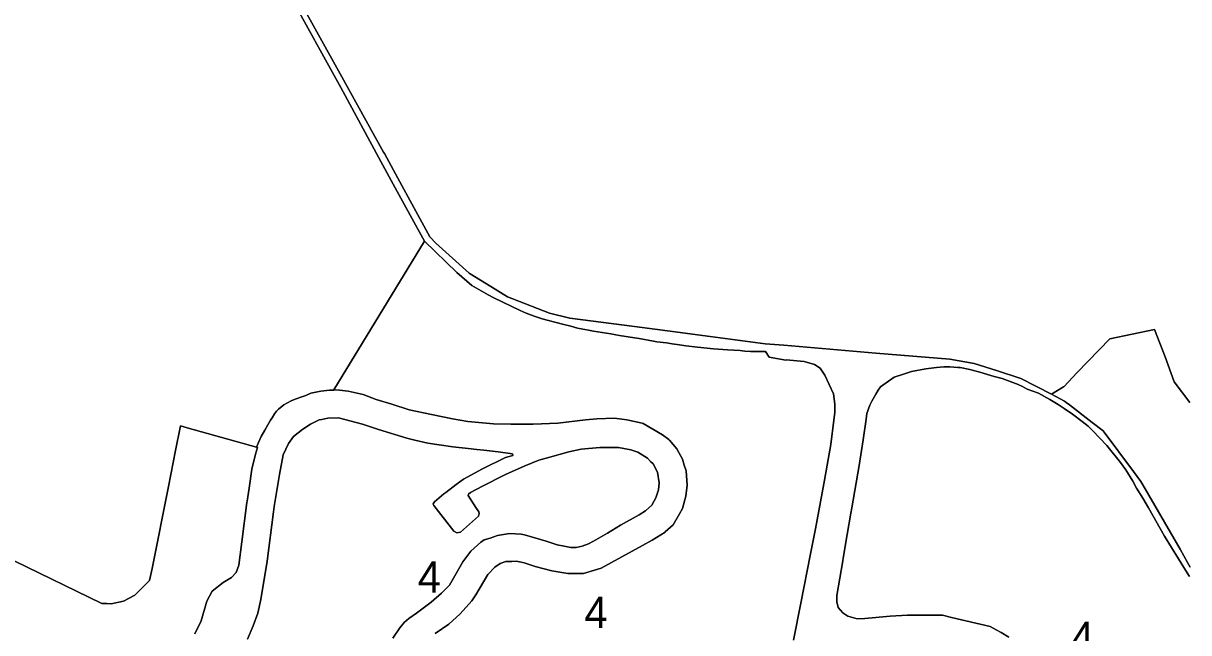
# Model space of a CAD drawing. Extents: x 598968 to 613553, y 4409678 to 4430833.
# Drawn here: x 610893 to 611339.8, y 4416609.3 to 4416843 of the extents above; entities that cross this region are included whole.
import ezdxf

# ---------------------------------------------------------------- set-up
doc = ezdxf.new("R2010")
doc.units = 0
for name, color, linetype in [('1', 7, 'Continuous'), ('Sòl Rústic Protegit', 7, 'Continuous'), ('Sòl Rústic Protegit - Alt Nivell de Protecció', 7, 'Continuous'), ('ZONA 4. CASES UNIFAMILIRAS AÏLLADES EN PARCEL.LES', 7, 'Continuous')]:
    doc.layers.add(name, color=color, linetype=linetype)

msp = doc.modelspace()

# ---------------------------------------------------------------- linework, layer by layer
at = {"layer": '1'}
for points in [[(611340.4703, 4416634.3506), (611339.421, 4416636.193), (611336.5169, 4416641.2922), (611332.8661, 4416647.7024), (611322.2536, 4416666.0055), (611321.4964, 4416667.3114), (611318.6806, 4416671.0975), (611307.1066, 4416686.6604), (611302.8637, 4416689.9208), (611294.1748, 4416696.5975), (611292.8617, 4416697.6065), (611292.207, 4416698.1096), (611287.2312, 4416700.7078), (611275.5474, 4416706.8087), (611266.1752, 4416709.7685), (611266.1698, 4416709.7702), (611257.6278, 4416712.4679), (611248.2281, 4416714.1276), (611219.9061, 4416716.5237), (611211.1119, 4416717.2678), (611184.6606, 4416719.5056), (611177.4599, 4416720.1149), (611156.3914, 4416722.8816), (611140.0057, 4416725.0334), (611135.0952, 4416725.6783), (611127.416, 4416726.6867), (611102.5516, 4416729.952), (611094.7018, 4416731.7716), (611080.3379, 4416737.4735), (611078.6822, 4416738.1308), (611072.3046, 4416742.0605), (611064.399, 4416746.9319), (611064.0125, 4416747.17), (611051.1328, 4416758.6293), (611048.8928, 4416761.0792), (611036.6372, 4416783.5263), (611031.4692, 4416792.9921), (611031.1632, 4416793.5526), (611014.5492, 4416823.542), (610996.5766, 4416855.9839)], [(610889.5487, 4416636.874), (610923.0883, 4416620.5149), (610924.9787, 4416620.4311), (610926.6983, 4416620.3549), (610931.4782, 4416621.355), (610935.7282, 4416623.715), (610941.4481, 4416629.2451), (610942.3873, 4416633.9202), (610948.6979, 4416665.3346), (610951.3988, 4416679.184), (610953.2378, 4416688.6144), (610955.7762, 4416687.8964), (610982.3887, 4416680.369), (610982.4015, 4416680.3985), (610982.4647, 4416680.5442), (610982.5502, 4416680.7415), (610983.1674, 4416682.1651), (610984.1574, 4416684.555), (610985.6274, 4416686.995), (610986.7073, 4416688.955), (610987.7473, 4416690.755), (610988.4873, 4416691.725), (610989.3173, 4416693.195), (610990.0973, 4416694.265), (610990.9073, 4416694.955), (610992.9572, 4416696.705), (610995.6972, 4416698.2051), (610997.2872, 4416698.8151), (611000.1972, 4416699.8851), (611001.3871, 4416700.2451), (611003.2871, 4416701.1652), (611007.0471, 4416701.8952), (611010.417, 4416702.3353), (611012.047, 4416702.3252), (611012.067, 4416702.3582), (611046.7764, 4416759.3851), (611042.6965, 4416766.8549), (611035.6093, 4416779.9183), (611030.1391, 4416790.0016), (611014.7467, 4416818.3737), (611012.8397, 4416821.8304), (610996.9169, 4416850.6929)], [(610996.9169, 4416850.6929), (611012.8397, 4416821.8304), (611014.7467, 4416818.3737), (611030.1391, 4416790.0016), (611035.6093, 4416779.9183), (611042.6965, 4416766.8549), (611046.7764, 4416759.3851), (611059.1863, 4416747.4354), (611064.9462, 4416742.4157), (611071.2962, 4416738.8158), (611073.4561, 4416737.7259), (611083.536, 4416732.8361), (611085.866, 4416731.7662), (611088.856, 4416730.6062), (611091.9159, 4416729.6363), (611099.7158, 4416727.5865), (611102.9558, 4416726.8865), (611105.5459, 4416726.0466), (611109.6958, 4416725.2367), (611111.6458, 4416724.8867), (611118.3357, 4416723.8269), (611120.2557, 4416723.4469), (611121.6057, 4416723.2169), (611127.3756, 4416722.387), (611129.1956, 4416722.0871), (611134.6355, 4416721.0971), (611135.8855, 4416720.8672), (611139.6254, 4416720.4173), (611141.8554, 4416720.0673), (611144.6454, 4416719.6374), (611146.9953, 4416719.2774), (611151.5553, 4416718.8075), (611157.6852, 4416718.1976), (611163.0251, 4416717.7977), (611167.8151, 4416717.4778), (611169.7151, 4416717.2179), (611171.895, 4416717.1479), (611177.615, 4416717.158), (611179.0049, 4416714.9481), (611185.3849, 4416713.8182), (611185.4549, 4416713.9782), (611192.4048, 4416713.2983), (611196.3947, 4416712.1883), (611198.5247, 4416710.7584), (611200.3647, 4416708.0385), (611203.6247, 4416700.8987), (611204.2143, 4416696.8614), (611204.1747, 4416693.7418), (611203.1591, 4416685.6628), (611202.6247, 4416681.412), (611200.2248, 4416667.8221), (611199.9648, 4416666.3422), (611196.7049, 4416649.1023), (611194.8949, 4416639.5124), (611191.175, 4416620.6127), (611188.325, 4416606.3928)], [(611270.9439, 4416607.5643), (611268.004, 4416609.3142), (611265.984, 4416610.4342), (611263.724, 4416611.6541), (611248.8729, 4416615.1396), (611245.4043, 4416615.9537), (611240.1644, 4416615.9936), (611236.7244, 4416616.0135), (611233.5945, 4416616.0335), (611231.9744, 4416615.943), (611225.3646, 4416615.6534), (611215.6947, 4416614.6932), (611212.7847, 4416614.5932), (611209.1048, 4416615.5631), (611207.2248, 4416616.883), (611205.4148, 4416618.933), (611204.8855, 4416621.1303), (611204.9348, 4416623.5098), (611207.1847, 4416636.8497), (611207.356, 4416637.8394), (611208.9347, 4416646.9595), (611210.3347, 4416655.1094), (611210.7047, 4416657.1494), (611213.4722, 4416673.4296), (611215.0446, 4416683.2991), (611216.1645, 4416691.179), (611216.4945, 4416693.399), (611217.5345, 4416696.469), (611218.3945, 4416698.069), (611219.9145, 4416700.7589), (611220.8444, 4416702.2889), (611221.6344, 4416703.559), (611226.9144, 4416707.269), (611230.4843, 4416708.3891), (611233.5543, 4416709.4591), (611239.1243, 4416710.5091), (611243.0941, 4416710.9992), (611245.9041, 4416711.2792), (611248.2641, 4416711.1793), (611251.3546, 4416710.9823), (611252.184, 4416710.9294), (611255.934, 4416710.2495), (611259.7339, 4416709.1296), (611265.2338, 4416707.5897), (611268.2938, 4416706.7797), (611274.4437, 4416704.4699), (611276.0637, 4416703.6399), (611277.8937, 4416702.7), (611282.3036, 4416701.0801), (611286.6536, 4416698.7002), (611289.8235, 4416696.8203), (611292.0735, 4416695.2203), (611295.2935, 4416693.0904), (611298.9434, 4416690.3305), (611301.2734, 4416688.4506), (611303.0234, 4416686.8306), (611308.4933, 4416681.0708), (611313.6633, 4416674.491), (611315.7732, 4416671.781), (611318.4332, 4416667.3412), (611319.8732, 4416664.6512), (611322.2833, 4416660.9213), (611324.3932, 4416657.1214), (611330.6232, 4416646.2417), (611338.663, 4416633.2021), (611340.133, 4416630.8421)], [(611050.9267, 4416608.9704), (611056.1466, 4416612.5804), (611060.4866, 4416616.4804), (611064.9765, 4416621.5204), (611066.4565, 4416623.7704), (611071.1764, 4416631.5504), (611073.8063, 4416634.4304), (611075.9063, 4416635.7805), (611078.0263, 4416636.5705), (611080.3363, 4416636.6405), (611081.9662, 4416636.6905), (611083.8962, 4416636.2605), (611085.0062, 4416636.0106), (611089.2762, 4416634.6207), (611095.6961, 4416632.9908), (611101.796, 4416631.9409), (611107.786, 4416631.9611), (611112.076, 4416633.3011), (611114.5159, 4416634.0712), (611130.3657, 4416642.7313), (611134.1657, 4416644.8114), (611139.1056, 4416647.8914), (611139.1056, 4416647.9114), (611142.1455, 4416650.6914), (611144.5655, 4416654.8913), (611145.7655, 4416656.9613), (611147.0855, 4416661.6113), (611147.5539, 4416665.897), (611147.5554, 4416665.9112), (611147.1054, 4416671.3312), (611146.4454, 4416673.5811), (611145.7854, 4416675.811), (611143.5855, 4416679.7909), (611140.8055, 4416683.1508), (611140.5055, 4416683.3709), (611138.0855, 4416685.2008), (611130.6563, 4416689.4622), (611130.2556, 4416689.6606), (611124.4457, 4416690.9505), (611119.7057, 4416691.4904), (611112.8758, 4416691.3202), (611108.5659, 4416690.9302), (611098.0059, 4416689.59), (611088.4661, 4416689.1999), (611080.3462, 4416689.1997), (611079.8862, 4416689.1997), (611073.2962, 4416689.3896), (611063.4564, 4416690.3194), (611057.5364, 4416691.2892), (611049.5766, 4416692.9391), (611041.0066, 4416694.769), (611034.3168, 4416696.8789), (611028.3568, 4416698.7587), (611023.297, 4416700.5786), (611017.5669, 4416701.9484), (611014.207, 4416702.3484), (611012.067, 4416702.3582), (611012.047, 4416702.3252), (611010.417, 4416702.3353), (611007.0471, 4416701.8952), (611003.2871, 4416701.1652), (611001.3871, 4416700.2451), (611000.1972, 4416699.8851), (610997.2872, 4416698.8151), (610995.6972, 4416698.2051), (610992.9572, 4416696.705), (610990.9073, 4416694.955), (610990.0973, 4416694.265), (610989.3173, 4416693.195), (610988.4873, 4416691.725), (610987.7473, 4416690.755), (610986.7073, 4416688.955), (610985.6274, 4416686.995), (610984.1574, 4416684.555), (610983.1674, 4416682.1651), (610982.5502, 4416680.7415), (610982.4647, 4416680.5442), (610982.4015, 4416680.3985), (610982.3887, 4416680.369), (610982.8415, 4416680.241), (610982.0604, 4416677.7468), (610980.6737, 4416671.9346), (610979.5881, 4416664.7356), (610978.8224, 4416659.6596), (610978.7567, 4416659.1683), (610976.7394, 4416644.0765), (610975.6795, 4416635.1658), (610974.6425, 4416632.4005), (610972.8642, 4416630.4209), (610969.6222, 4416628.491), (610965.4134, 4416625.2367), (610963.35, 4416621.3341), (610961.184, 4416613.8732), (610958.7248, 4416608.878)], [(610978.9476, 4416606.7691), (610981.2076, 4416611.8791), (610982.9075, 4416616.8091), (610984.0775, 4416621.999), (610986.4575, 4416636.6989), (610988.9574, 4416655.6586), (610989.2175, 4416657.6086), (610991.2173, 4416669.9584), (610992.6473, 4416677.4583), (610994.7273, 4416681.8583), (610996.6372, 4416684.4883), (611000.1972, 4416687.3683), (611003.0971, 4416689.2984), (611006.4571, 4416690.8484), (611007.4771, 4416691.0984), (611009.807, 4416691.5985), (611013.827, 4416691.7285), (611023.0647, 4416689.2135), (611029.1468, 4416687.2188), (611040.008, 4416683.8504), (611043.1059, 4416683.1374), (611048.069, 4416681.9888), (611052.4228, 4416681.3347), (611057.7561, 4416680.588), (611063.625, 4416679.9563), (611066.9439, 4416679.5347), (611069.5442, 4416679.3003), (611075.045, 4416678.6424), (611080.6234, 4416677.8685), (611080.7396, 4416677.2879), (611080.7334, 4416677.286), (611077.8462, 4416676.4399), (611069.0863, 4416672.1198), (611061.8064, 4416668.1997), (611058.9865, 4416666.0497), (611055.0766, 4416663.0796), (611054.2365, 4416662.5696), (611050.6566, 4416659.5096), (611050.2166, 4416658.6396), (611050.2233, 4416658.62), (611050.2166, 4416658.6066), (611050.4266, 4416657.9966), (611058.1265, 4416648.1669), (611059.2165, 4416647.6069), (611060.6565, 4416647.8169), (611067.5964, 4416653.9269), (611067.828, 4416654.9358), (611067.8236, 4416654.9498), (611067.828, 4416654.9688), (611067.6164, 4416655.6499), (611066.5464, 4416657.2499), (611063.6374, 4416661.9083), (611063.6526, 4416662.3967), (611064.4139, 4416663.0336), (611069.0241, 4416665.5173), (611077.4062, 4416669.6469), (611078.1562, 4416670.0769), (611080.2562, 4416670.9369), (611085.0461, 4416673.157), (611090.736, 4416675.4971), (611094.8738, 4416676.5688), (611102.1159, 4416678.6872), (611106.8772, 4416679.6225), (611114.0335, 4416680.2608), (611120.1358, 4416680.3375), (611121.1851, 4416680.2936), (611126.0026, 4416679.3605), (611128.6358, 4416678.5677), (611132.2956, 4416676.2478), (611133.5056, 4416674.9478), (611134.5456, 4416673.9878), (611136.1517, 4416670.855), (611136.8734, 4416666.7403), (611136.5956, 4416664.0811), (611135.5756, 4416661.0211), (611133.9856, 4416658.1511), (611131.6358, 4416656.0011), (611129.1757, 4416654.4411), (611121.9958, 4416650.531), (611117.0599, 4416647.5017), (611111.6924, 4416644.4325), (611109.766, 4416643.3309), (611107.2785, 4416642.4112), (611105.0488, 4416642.0011), (611102.896, 4416641.9808), (611100.3533, 4416642.4852), (611097.7457, 4416643.0302), (611093.4851, 4416644.3309), (611091.2608, 4416645.0268), (611085.2262, 4416646.8405), (611083.9261, 4416647.0197), (611079.4488, 4416647.257), (611074.8684, 4416646.5091), (611072.0609, 4416645.5486), (611069.7464, 4416644.9302), (611068.4264, 4416644.0202), (611064.6302, 4416640.5255), (611063.4116, 4416638.9581), (611061.5972, 4416636.4496), (611056.3666, 4416627.5402), (611055.5366, 4416626.5702), (611053.3096, 4416624.4225), (611049.3371, 4416621.0065), (611043.7512, 4416616.7832), (611040.8344, 4416614.7402), (611039.0691, 4416613.232), (611037.339, 4416611.1665), (611034.741, 4416607.1495)], [(610958.7248, 4416608.878), (610961.184, 4416613.8732), (610963.35, 4416621.3341), (610965.4134, 4416625.2367), (610969.6222, 4416628.491), (610972.8642, 4416630.4209), (610974.6425, 4416632.4005), (610975.6795, 4416635.1658), (610976.7394, 4416644.0765), (610978.7567, 4416659.1683), (610978.8224, 4416659.6596), (610979.5881, 4416664.7356), (610980.6737, 4416671.9346), (610982.0604, 4416677.7468), (610982.8415, 4416680.241), (610982.3887, 4416680.369), (610955.7762, 4416687.8964), (610953.2378, 4416688.6144), (610951.3988, 4416679.184), (610948.6979, 4416665.3346), (610942.3873, 4416633.9202), (610941.4481, 4416629.2451), (610935.7282, 4416623.715), (610931.4782, 4416621.355), (610926.6983, 4416620.3549), (610924.9787, 4416620.4311), (610923.0883, 4416620.5149), (610889.5487, 4416636.874)]]:
    msp.add_lwpolyline(points, dxfattribs=at)
at = {"layer": 'Sòl Rústic Protegit'}
msp.add_lwpolyline([(611340.2427, 4416697.51), (611334.2427, 4416705.51), (611330.8051, 4416715.01), (611326.6801, 4416725.51), (611309.5551, 4416722.01), (611297.1177, 4416709.01), (611291.9927, 4416703.51), (611291.8677, 4416703.51), (611287.2312, 4416700.7078), (611292.207, 4416698.1096), (611292.8617, 4416697.6065), (611294.1748, 4416696.5975), (611302.8637, 4416689.9208), (611307.1066, 4416686.6604), (611318.6806, 4416671.0975), (611321.4964, 4416667.3114), (611322.2536, 4416666.0055), (611332.8661, 4416647.7024), (611336.5169, 4416641.2922), (611339.421, 4416636.193), (611340.4703, 4416634.3506)], dxfattribs=at)
at = {"layer": 'Sòl Rústic Protegit - Alt Nivell de Protecció'}
msp.add_lwpolyline([(610996.5766, 4416855.9839), (611014.5492, 4416823.542), (611031.1632, 4416793.5526), (611031.4692, 4416792.9921), (611036.6372, 4416783.5263), (611048.8928, 4416761.0792), (611051.1328, 4416758.6293), (611064.0125, 4416747.17), (611064.399, 4416746.9319), (611072.3046, 4416742.0605), (611078.6822, 4416738.1308), (611080.3379, 4416737.4735), (611094.7018, 4416731.7716), (611102.5516, 4416729.952), (611127.416, 4416726.6867), (611135.0952, 4416725.6783), (611140.0057, 4416725.0334), (611156.3914, 4416722.8816), (611177.4599, 4416720.1149), (611184.6606, 4416719.5056), (611211.1119, 4416717.2678), (611219.9061, 4416716.5237), (611248.2281, 4416714.1276), (611257.6278, 4416712.4679), (611266.1698, 4416709.7702), (611266.1752, 4416709.7685), (611275.5474, 4416706.8087), (611287.2312, 4416700.7078), (611291.8677, 4416703.51), (611291.9927, 4416703.51), (611297.1177, 4416709.01), (611309.5551, 4416722.01), (611326.6801, 4416725.51), (611330.8051, 4416715.01), (611334.2427, 4416705.51), (611340.2427, 4416697.51)], dxfattribs=at)
at = {"layer": 'ZONA 4. CASES UNIFAMILIRAS AÏLLADES EN PARCEL.LES'}
for points in [[(611188.325, 4416606.3928), (611191.175, 4416620.6127), (611194.8949, 4416639.5124), (611196.7049, 4416649.1023), (611199.9648, 4416666.3422), (611200.2248, 4416667.8221), (611202.6247, 4416681.412), (611203.1591, 4416685.6628), (611204.1747, 4416693.7418), (611204.2143, 4416696.8614), (611203.6247, 4416700.8987), (611200.3647, 4416708.0385), (611198.5247, 4416710.7584), (611196.3947, 4416712.1883), (611192.4048, 4416713.2983), (611185.4549, 4416713.9782), (611185.3849, 4416713.8182), (611179.0049, 4416714.9481), (611177.615, 4416717.158), (611171.895, 4416717.1479), (611169.7151, 4416717.2179), (611167.8151, 4416717.4778), (611163.0251, 4416717.7977), (611157.6852, 4416718.1976), (611151.5553, 4416718.8075), (611146.9953, 4416719.2774), (611144.6454, 4416719.6374), (611141.8554, 4416720.0673), (611139.6254, 4416720.4173), (611135.8855, 4416720.8672), (611134.6355, 4416721.0971), (611129.1956, 4416722.0871), (611127.3756, 4416722.387), (611121.6057, 4416723.2169), (611120.2557, 4416723.4469), (611118.3357, 4416723.8269), (611111.6458, 4416724.8867), (611109.6958, 4416725.2367), (611105.5459, 4416726.0466), (611102.9558, 4416726.8865), (611099.7158, 4416727.5865), (611091.9159, 4416729.6363), (611088.856, 4416730.6062), (611085.866, 4416731.7662), (611083.536, 4416732.8361), (611073.4561, 4416737.7259), (611071.2962, 4416738.8158), (611064.9462, 4416742.4157), (611059.1863, 4416747.4354), (611046.7764, 4416759.3851), (611012.067, 4416702.3582), (611014.207, 4416702.3484), (611017.5669, 4416701.9484), (611023.297, 4416700.5786), (611028.3568, 4416698.7587), (611034.3168, 4416696.8789), (611041.0066, 4416694.769), (611049.5766, 4416692.9391), (611057.5364, 4416691.2892), (611063.4564, 4416690.3194), (611073.2962, 4416689.3896), (611079.8862, 4416689.1997), (611080.3462, 4416689.1997), (611088.4661, 4416689.1999), (611098.0059, 4416689.59), (611108.5659, 4416690.9302), (611112.8758, 4416691.3202), (611119.7057, 4416691.4904), (611124.4457, 4416690.9505), (611130.2556, 4416689.6606), (611130.6563, 4416689.4622), (611138.0855, 4416685.2008), (611140.5055, 4416683.3709), (611140.8055, 4416683.1508), (611143.5855, 4416679.7909), (611145.7854, 4416675.811), (611146.4454, 4416673.5811), (611147.1054, 4416671.3312), (611147.5554, 4416665.9112), (611147.5539, 4416665.897), (611147.0855, 4416661.6113), (611145.7655, 4416656.9613), (611144.5655, 4416654.8913), (611142.1455, 4416650.6914), (611139.1056, 4416647.9114), (611139.1056, 4416647.8914), (611134.1657, 4416644.8114), (611130.3657, 4416642.7313), (611114.5159, 4416634.0712), (611112.076, 4416633.3011), (611107.786, 4416631.9611), (611101.796, 4416631.9409), (611095.6961, 4416632.9908), (611089.2762, 4416634.6207), (611085.0062, 4416636.0106), (611083.8962, 4416636.2605), (611081.9662, 4416636.6905), (611080.3363, 4416636.6405), (611078.0263, 4416636.5705), (611075.9063, 4416635.7805), (611073.8063, 4416634.4304), (611071.1764, 4416631.5504), (611066.4565, 4416623.7704), (611064.9765, 4416621.5204), (611060.4866, 4416616.4804), (611056.1466, 4416612.5804), (611050.9267, 4416608.9704)], [(611340.133, 4416630.8421), (611338.663, 4416633.2021), (611330.6232, 4416646.2417), (611324.3932, 4416657.1214), (611322.2833, 4416660.9213), (611319.8732, 4416664.6512), (611318.4332, 4416667.3412), (611315.7732, 4416671.781), (611313.6633, 4416674.491), (611308.4933, 4416681.0708), (611303.0234, 4416686.8306), (611301.2734, 4416688.4506), (611298.9434, 4416690.3305), (611295.2935, 4416693.0904), (611292.0735, 4416695.2203), (611289.8235, 4416696.8203), (611286.6536, 4416698.7002), (611282.3036, 4416701.0801), (611277.8937, 4416702.7), (611276.0637, 4416703.6399), (611274.4437, 4416704.4699), (611268.2938, 4416706.7797), (611265.2338, 4416707.5897), (611259.7339, 4416709.1296), (611255.934, 4416710.2495), (611252.184, 4416710.9294), (611251.3546, 4416710.9823), (611248.2641, 4416711.1793), (611245.9041, 4416711.2792), (611243.0941, 4416710.9992), (611239.1243, 4416710.5091), (611233.5543, 4416709.4591), (611230.4843, 4416708.3891), (611226.9144, 4416707.269), (611221.6344, 4416703.559), (611220.8444, 4416702.2889), (611219.9145, 4416700.7589), (611218.3945, 4416698.069), (611217.5345, 4416696.469), (611216.4945, 4416693.399), (611216.1645, 4416691.179), (611215.0446, 4416683.2991), (611213.4722, 4416673.4296), (611210.7047, 4416657.1494), (611210.3347, 4416655.1094), (611208.9347, 4416646.9595), (611207.356, 4416637.8394), (611207.1847, 4416636.8497), (611204.9348, 4416623.5098), (611204.8855, 4416621.1303), (611205.4148, 4416618.933), (611207.2248, 4416616.883), (611209.1048, 4416615.5631), (611212.7847, 4416614.5932), (611215.6947, 4416614.6932), (611225.3646, 4416615.6534), (611231.9744, 4416615.943), (611233.5945, 4416616.0335), (611236.7244, 4416616.0135), (611240.1644, 4416615.9936), (611245.4043, 4416615.9537), (611248.8729, 4416615.1396), (611263.724, 4416611.6541), (611265.984, 4416610.4342), (611268.004, 4416609.3142), (611270.9439, 4416607.5643)], [(611034.741, 4416607.1495), (611037.339, 4416611.1665), (611039.0691, 4416613.232), (611040.8344, 4416614.7402), (611043.7512, 4416616.7832), (611049.3371, 4416621.0065), (611053.3096, 4416624.4225), (611055.5366, 4416626.5702), (611056.3666, 4416627.5402), (611061.5972, 4416636.4496), (611063.4116, 4416638.9581), (611064.6302, 4416640.5255), (611068.4264, 4416644.0202), (611069.7464, 4416644.9302), (611072.0609, 4416645.5486), (611074.8684, 4416646.5091), (611079.4488, 4416647.257), (611083.9261, 4416647.0197), (611085.2262, 4416646.8405), (611091.2608, 4416645.0268), (611093.4851, 4416644.3309), (611097.7457, 4416643.0302), (611100.3533, 4416642.4852), (611102.896, 4416641.9808), (611105.0488, 4416642.0011), (611107.2785, 4416642.4112), (611109.766, 4416643.3309), (611111.6924, 4416644.4325), (611117.0599, 4416647.5017), (611121.9958, 4416650.531), (611129.1757, 4416654.4411), (611131.6358, 4416656.0011), (611133.9856, 4416658.1511), (611135.5756, 4416661.0211), (611136.5956, 4416664.0811), (611136.8734, 4416666.7403), (611136.1517, 4416670.855), (611134.5456, 4416673.9878), (611133.5056, 4416674.9478), (611132.2956, 4416676.2478), (611128.6358, 4416678.5677), (611126.0026, 4416679.3605), (611121.1851, 4416680.2936), (611120.1358, 4416680.3375), (611114.0335, 4416680.2608), (611106.8772, 4416679.6225), (611102.1159, 4416678.6872), (611094.8738, 4416676.5688), (611090.736, 4416675.4971), (611085.0461, 4416673.157), (611080.2562, 4416670.9369), (611078.1562, 4416670.0769), (611077.4062, 4416669.6469), (611069.0241, 4416665.5173), (611064.4139, 4416663.0336), (611063.6526, 4416662.3967), (611063.6374, 4416661.9083), (611066.5464, 4416657.2499), (611067.6164, 4416655.6499), (611067.828, 4416654.9688), (611067.8236, 4416654.9498), (611067.828, 4416654.9358), (611067.5964, 4416653.9269), (611060.6565, 4416647.8169), (611059.2165, 4416647.6069), (611058.1265, 4416648.1669), (611050.4266, 4416657.9966), (611050.2166, 4416658.6066), (611050.2233, 4416658.62), (611050.2166, 4416658.6396), (611050.6566, 4416659.5096), (611054.2365, 4416662.5696), (611055.0766, 4416663.0796), (611058.9865, 4416666.0497), (611061.8064, 4416668.1997), (611069.0863, 4416672.1198), (611077.8462, 4416676.4399), (611080.7334, 4416677.286), (611080.7396, 4416677.2879), (611080.6234, 4416677.8685), (611075.045, 4416678.6424), (611069.5442, 4416679.3003), (611066.9439, 4416679.5347), (611063.625, 4416679.9563), (611057.7561, 4416680.588), (611052.4228, 4416681.3347), (611048.069, 4416681.9888), (611043.1059, 4416683.1374), (611040.008, 4416683.8504), (611029.1468, 4416687.2188), (611023.0647, 4416689.2135), (611013.827, 4416691.7285), (611009.807, 4416691.5985), (611007.4771, 4416691.0984), (611006.4571, 4416690.8484), (611003.0971, 4416689.2984), (611000.1972, 4416687.3683), (610996.6372, 4416684.4883), (610994.7273, 4416681.8583), (610992.6473, 4416677.4583), (610991.2173, 4416669.9584), (610989.2175, 4416657.6086), (610988.9574, 4416655.6586), (610986.4575, 4416636.6989), (610984.0775, 4416621.999), (610982.9075, 4416616.8091), (610981.2076, 4416611.8791), (610978.9476, 4416606.7691)]]:
    msp.add_lwpolyline(points, dxfattribs=at)

# ---------------------------------------------------------------- texts
for p in [(611044.2453, 4416624.6679), (611108.1406, 4416611.0593), (611294.6541, 4416601.4967)]:
    msp.add_text('4', height=12, dxfattribs=at).set_placement(p)

doc.saveas('drawing.dxf')
